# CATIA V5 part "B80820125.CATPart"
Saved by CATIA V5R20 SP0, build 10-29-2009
Part number: B80820125
Revision: 3
Definition: design
Nomenclature: B80820125
Source: made
Description: NOT SPECIFIED
Bounding box of the stored display mesh (mm): x -11.818 to 11.818, y -12 to 12, z 0 to 125
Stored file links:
  C:\Users\Raffaele\Desktop\3D X SITO CF\BOLEX\4-PILLAR REF 808\B80820125.CATPart
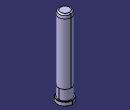
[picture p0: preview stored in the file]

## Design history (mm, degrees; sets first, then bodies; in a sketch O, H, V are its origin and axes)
Body1 "MANIFOLD_SOLID_BREP #450" (main body)
  Solid1: solid without history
